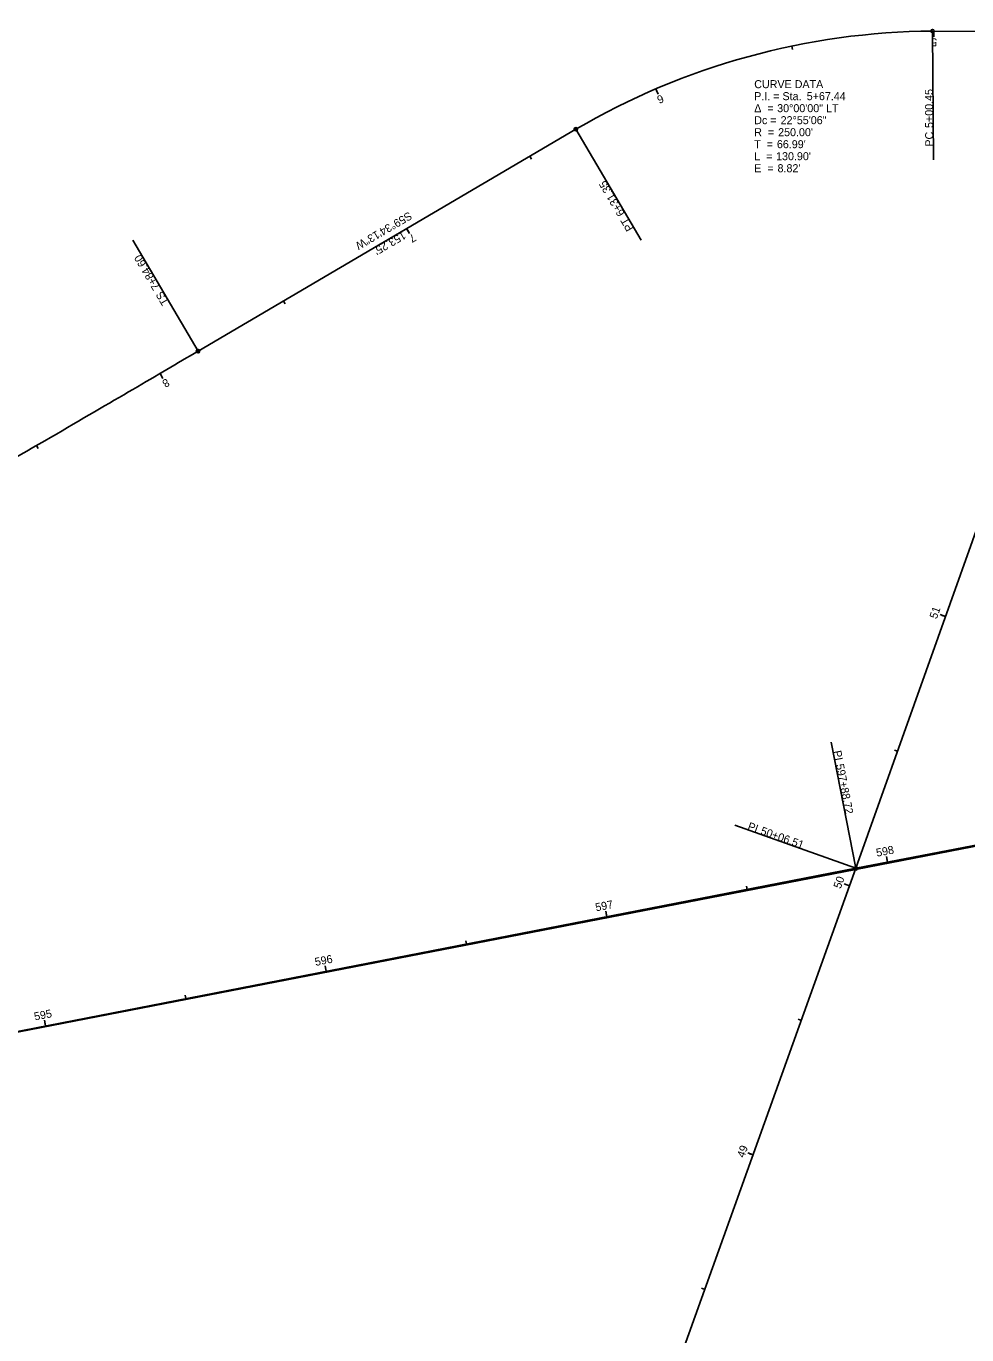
# Model space of a CAD drawing. Extents: x 2255781 to 2266449, y 734189 to 743342.
# Drawn here: x 2262943.9 to 2263272.9, y 741958.3 to 742416.1 of the extents above; entities that cross this region are included whole.
import ezdxf

# ---------------------------------------------------------------- set-up
doc = ezdxf.new("R2010")
doc.units = 0
for name, color, linetype in [('GE_X_Alignment', 7, 'Continuous'), ('GE_X_Alignment_1000_Bearings', 7, 'Continuous'), ('GE_X_Alignment_1000_Cardinal_Points', 7, 'Continuous'), ('GE_X_Alignment_1000_Curve_Data', 7, 'Continuous'), ('GE_X_Alignment_1000_Distances', 7, 'Continuous'), ('GE_X_Alignment_1000_Stations', 7, 'Continuous'), ('GE_X_Alignment_100_Bearings', 7, 'Continuous'), ('GE_X_Alignment_100_Cardinal_Points', 7, 'Continuous'), ('GE_X_Alignment_100_Curve_Data', 7, 'Continuous'), ('GE_X_Alignment_100_Distances', 7, 'Continuous'), ('GE_X_Alignment_100_Stations', 7, 'Continuous'), ('GE_X_Alignment_500_Bearings', 7, 'Continuous'), ('GE_X_Alignment_500_Cardinal_Points', 7, 'Continuous'), ('GE_X_Alignment_500_Curve_Data', 7, 'Continuous'), ('GE_X_Alignment_500_Distances', 7, 'Continuous'), ('GE_X_Alignment_500_Stations', 7, 'Continuous'), ('SC_Scratch4', 7, 'Continuous')]:
    doc.layers.add(name, color=color, linetype=linetype)

msp = doc.modelspace()

# ---------------------------------------------------------------- linework, layer by layer
at = {"layer": 'GE_X_Alignment'}
for p, q in [((2263234.07, 742121.49), (2263662.12, 743324.91)), ((2263338.12, 742414.02), (2263260.89, 742414.36)), ((2263234.07, 742121.49), (2264717.55, 742410.01)), ((2263136.12, 742380.02), (2263003.98, 742302.4)), ((2262524.08, 741983.4), (2263234.07, 742121.49)), ((2262767.69, 740821.08), (2263234.07, 742121.49))]:
    msp.add_line(p, q, dxfattribs=at)
msp.add_arc((2263262.59, 742164.37), 250, 90.3896, 120.3897, dxfattribs=at)
msp.add_open_spline([(2263003.98, 742302.4), (2262996.8, 742298.18), (2262982.43, 742289.73), (2262953.66, 742272.9), (2262917.56, 742252.1), (2262881.09, 742231.92), (2262851.61, 742216.36), (2262836.76, 742208.81), (2262829.3, 742205.1)], degree=3, dxfattribs=at)
at = {"layer": 'GE_X_Alignment_1000_Cardinal_Points'}
for p, q in [((2263260.89, 742414.36), (2263261.2, 742369.36)), ((2263136.12, 742380.02), (2263158.91, 742341.22)), ((2263003.98, 742302.4), (2262981.17, 742341.19)), ((2263234.07, 742121.49), (2263225.47, 742165.66)), ((2263234.07, 742121.49), (2263191.67, 742136.57))]:
    msp.add_line(p, q, dxfattribs=at)
for centre in [(2263260.89, 742414.36), (2263136.12, 742380.02), (2263003.98, 742302.4), (2263234.07, 742121.49), (2263234.07, 742121.49)]:
    msp.add_circle(centre, 0.6, dxfattribs=at)
at = {"layer": 'GE_X_Alignment_1000_Stations'}
for p, q in [((2263261.34, 742414.36), (2263261.34, 742413.16)), ((2263231.87, 742115.36), (2263229.98, 742116.04)), ((2262950.66, 742066.37), (2262950.43, 742067.55))]:
    msp.add_line(p, q, dxfattribs=at)
at = {"layer": 'GE_X_Alignment_100_Cardinal_Points'}
for p, q in [((2263260.89, 742414.36), (2263261.2, 742369.36)), ((2263136.12, 742380.02), (2263158.91, 742341.22)), ((2263003.98, 742302.4), (2262981.17, 742341.19)), ((2263234.07, 742121.49), (2263225.47, 742165.66)), ((2263234.07, 742121.49), (2263191.67, 742136.57))]:
    msp.add_line(p, q, dxfattribs=at)
for centre in [(2263260.89, 742414.36), (2263136.12, 742380.02), (2263003.98, 742302.4), (2263234.07, 742121.49), (2263234.07, 742121.49)]:
    msp.add_circle(centre, 0.6, dxfattribs=at)
at = {"layer": 'GE_X_Alignment_100_Stations'}
for p, q in [((2263261.34, 742414.36), (2263261.33, 742412.36)), ((2263211.7, 742409.13), (2263211.94, 742407.96)), ((2263164.09, 742394.14), (2263164.87, 742392.3)), ((2263120.04, 742370.57), (2263120.65, 742369.54)), ((2263076.93, 742345.25), (2263077.94, 742343.52)), ((2263033.82, 742319.92), (2263034.42, 742318.89)), ((2262990.7, 742294.6), (2262991.72, 742292.87)), ((2262947.52, 742269.4), (2262948.12, 742268.36)), ((2263265.4, 742209.57), (2263263.51, 742210.24)), ((2263248.64, 742162.46), (2263247.51, 742162.87)), ((2263245.14, 742123.64), (2263244.76, 742125.61)), ((2263231.87, 742115.36), (2263229.98, 742116.04)), ((2263196.06, 742114.1), (2263195.83, 742115.28)), ((2263146.98, 742104.55), (2263146.6, 742106.52)), ((2263097.9, 742095.01), (2263097.67, 742096.18)), ((2263048.82, 742085.46), (2263048.43, 742087.42)), ((2262999.74, 742075.91), (2262999.51, 742077.09)), ((2262950.66, 742066.37), (2262950.27, 742068.33)), ((2263214.99, 742068.3), (2263213.86, 742068.7)), ((2263198.11, 742021.23), (2263196.23, 742021.91)), ((2263181.23, 741974.17), (2263180.1, 741974.57))]:
    msp.add_line(p, q, dxfattribs=at)
at = {"layer": 'GE_X_Alignment_500_Cardinal_Points'}
for p, q in [((2263260.89, 742414.36), (2263261.2, 742369.36)), ((2263136.12, 742380.02), (2263158.91, 742341.22)), ((2263003.98, 742302.4), (2262981.17, 742341.19)), ((2263234.07, 742121.49), (2263225.47, 742165.66)), ((2263234.07, 742121.49), (2263191.67, 742136.57))]:
    msp.add_line(p, q, dxfattribs=at)
for centre in [(2263260.89, 742414.36), (2263136.12, 742380.02), (2263003.98, 742302.4), (2263234.07, 742121.49), (2263234.07, 742121.49)]:
    msp.add_circle(centre, 0.6, dxfattribs=at)
at = {"layer": 'GE_X_Alignment_500_Stations'}
for p, q in [((2263261.34, 742414.36), (2263261.33, 742412.36)), ((2263164.09, 742394.14), (2263164.56, 742393.04)), ((2263076.93, 742345.25), (2263077.54, 742344.21)), ((2262990.7, 742294.6), (2262991.31, 742293.56)), ((2263265.4, 742209.57), (2263264.27, 742209.98)), ((2263245.14, 742123.64), (2263244.91, 742124.82)), ((2263231.87, 742115.36), (2263229.98, 742116.04)), ((2263146.98, 742104.55), (2263146.75, 742105.73)), ((2263048.82, 742085.46), (2263048.59, 742086.64)), ((2262950.66, 742066.37), (2262950.27, 742068.33)), ((2263198.11, 742021.23), (2263196.98, 742021.64))]:
    msp.add_line(p, q, dxfattribs=at)
at = {"layer": 'SC_Scratch4'}
for p, q in [((2263234.07, 742121.1), (2264717.66, 742409.08)), ((2262524.04, 741983.27), (2263234.07, 742121.1))]:
    msp.add_line(p, q, dxfattribs=at)

# ---------------------------------------------------------------- texts
at = {"layer": 'GE_X_Alignment_1000_Bearings'}
msp.add_text('S59°34\'13"W', height=2.8, rotation=210.4298, dxfattribs=at).set_placement((2263077.76, 742351.3))
at = {"layer": 'GE_X_Alignment_1000_Cardinal_Points'}
for s, rotation, p in [('5+00.45', 90.3896, (2263261.07, 742380.47)), ('PC', 90.3896, (2263261.12, 742373.95)), ('6+31.35', 120.4298, (2263153.36, 742350.58)), ('PT', 120.4298, (2263156.44, 742345.34)), ('7+84.60', 120.4521, (2262990.81, 742324.71)), ('TS', 120.4521, (2262993.9, 742319.46)), ('PI', 281.0061, (2263226.15, 742162.43)), ('597+88.72', 281.0061, (2263227.06, 742157.74)), ('PI', 340.4195, (2263195.97, 742135.09)), ('50+06.51', 340.4195, (2263200.48, 742133.49))]:
    msp.add_text(s, height=2.8, rotation=rotation, dxfattribs=at).set_placement(p)
at = {"layer": 'GE_X_Alignment_1000_Curve_Data'}
for s, p in [('CURVE DATA', (2263198.51, 742394.39)), ('P.I. = Sta. ', (2263198.51, 742390.19)), ('5+67.44', (2263216.87, 742390.19)), ('Δ  = ', (2263198.51, 742385.99)), ('30°00\'00" LT', (2263206.53, 742385.99)), ('Dc = ', (2263198.51, 742381.79)), ('22°55\'06"', (2263207.74, 742381.79)), ('R  = ', (2263198.51, 742377.59)), ("250.00'", (2263206.87, 742377.59)), ('T  = ', (2263198.51, 742373.39)), ("66.99'", (2263206.44, 742373.39)), ('L  = ', (2263198.51, 742369.19)), ('E  = ', (2263198.51, 742364.99)), ("130.90'", (2263206.15, 742369.19)), ("8.82'", (2263206.66, 742364.99))]:
    msp.add_text(s, height=2.8, dxfattribs=at).set_placement(p)
at = {"layer": 'GE_X_Alignment_1000_Distances'}
msp.add_text("153.25'", height=2.8, rotation=210.4298, dxfattribs=at).set_placement((2263075.67, 742344.45))
at = {"layer": 'GE_X_Alignment_1000_Stations'}
msp.add_text('50', height=2.8, rotation=70.2703, dxfattribs=at).set_placement((2263228.73, 742114.16))
at = {"layer": 'GE_X_Alignment_100_Bearings'}
msp.add_text('S59°34\'13"W', height=2.8, rotation=210.4298, dxfattribs=at).set_placement((2263077.76, 742351.3))
at = {"layer": 'GE_X_Alignment_100_Cardinal_Points'}
for s, rotation, p in [('5+00.45', 90.3896, (2263261.07, 742380.47)), ('PC', 90.3896, (2263261.12, 742373.95)), ('6+31.35', 120.4298, (2263153.36, 742350.58)), ('PT', 120.4298, (2263156.44, 742345.34)), ('7+84.60', 120.4521, (2262990.81, 742324.71)), ('TS', 120.4521, (2262993.9, 742319.46)), ('PI', 281.0061, (2263226.15, 742162.43)), ('597+88.72', 281.0061, (2263227.06, 742157.74)), ('PI', 340.4195, (2263195.97, 742135.09)), ('50+06.51', 340.4195, (2263200.48, 742133.49))]:
    msp.add_text(s, height=2.8, rotation=rotation, dxfattribs=at).set_placement(p)
at = {"layer": 'GE_X_Alignment_100_Curve_Data'}
for s, p in [('CURVE DATA', (2263198.51, 742394.39)), ('P.I. = Sta. ', (2263198.51, 742390.19)), ('5+67.44', (2263216.87, 742390.19)), ('Δ  = ', (2263198.51, 742385.99)), ('30°00\'00" LT', (2263206.53, 742385.99)), ('Dc = ', (2263198.51, 742381.79)), ('22°55\'06"', (2263207.74, 742381.79)), ('R  = ', (2263198.51, 742377.59)), ("250.00'", (2263206.87, 742377.59)), ('T  = ', (2263198.51, 742373.39)), ("66.99'", (2263206.44, 742373.39)), ('L  = ', (2263198.51, 742369.19)), ('E  = ', (2263198.51, 742364.99)), ("130.90'", (2263206.15, 742369.19)), ("8.82'", (2263206.66, 742364.99))]:
    msp.add_text(s, height=2.8, dxfattribs=at).set_placement(p)
at = {"layer": 'GE_X_Alignment_100_Distances'}
msp.add_text("153.25'", height=2.8, rotation=210.4298, dxfattribs=at).set_placement((2263075.67, 742344.45))
at = {"layer": 'GE_X_Alignment_100_Stations'}
for s, rotation, p in [('5', 179.7497, (2263262.45, 742411.81)), ('6', 203.2048, (2263166.11, 742392.24)), ('7', 210.4298, (2263079.2, 742343.68)), ('8', 210.4283, (2262992.95, 742292.96)), ('51', 70.4195, (2263262.32, 742208.52)), ('598', 11.0061, (2263241.43, 742125.52)), ('50', 70.2703, (2263228.73, 742114.16)), ('597', 11.0061, (2263143.21, 742106.41)), ('596', 11.0061, (2263045.11, 742087.33)), ('595', 11.0061, (2262946.94, 742068.24)), ('49', 70.2703, (2263194.98, 742020.05))]:
    msp.add_text(s, height=2.8, rotation=rotation, dxfattribs=at).set_placement(p)
at = {"layer": 'GE_X_Alignment_500_Bearings'}
msp.add_text('S59°34\'13"W', height=2.8, rotation=210.4298, dxfattribs=at).set_placement((2263077.76, 742351.3))
at = {"layer": 'GE_X_Alignment_500_Cardinal_Points'}
for s, rotation, p in [('5+00.45', 90.3896, (2263261.07, 742380.47)), ('PC', 90.3896, (2263261.12, 742373.95)), ('6+31.35', 120.4298, (2263153.36, 742350.58)), ('PT', 120.4298, (2263156.44, 742345.34)), ('7+84.60', 120.4521, (2262990.81, 742324.71)), ('TS', 120.4521, (2262993.9, 742319.46)), ('PI', 281.0061, (2263226.15, 742162.43)), ('597+88.72', 281.0061, (2263227.06, 742157.74)), ('PI', 340.4195, (2263195.97, 742135.09)), ('50+06.51', 340.4195, (2263200.48, 742133.49))]:
    msp.add_text(s, height=2.8, rotation=rotation, dxfattribs=at).set_placement(p)
at = {"layer": 'GE_X_Alignment_500_Curve_Data'}
for s, p in [('CURVE DATA', (2263198.51, 742394.39)), ('P.I. = Sta. ', (2263198.51, 742390.19)), ('5+67.44', (2263216.87, 742390.19)), ('Δ  = ', (2263198.51, 742385.99)), ('30°00\'00" LT', (2263206.53, 742385.99)), ('Dc = ', (2263198.51, 742381.79)), ('22°55\'06"', (2263207.74, 742381.79)), ('R  = ', (2263198.51, 742377.59)), ("250.00'", (2263206.87, 742377.59)), ('T  = ', (2263198.51, 742373.39)), ("66.99'", (2263206.44, 742373.39)), ('L  = ', (2263198.51, 742369.19)), ('E  = ', (2263198.51, 742364.99)), ("130.90'", (2263206.15, 742369.19)), ("8.82'", (2263206.66, 742364.99))]:
    msp.add_text(s, height=2.8, dxfattribs=at).set_placement(p)
at = {"layer": 'GE_X_Alignment_500_Distances'}
msp.add_text("153.25'", height=2.8, rotation=210.4298, dxfattribs=at).set_placement((2263075.67, 742344.45))
at = {"layer": 'GE_X_Alignment_500_Stations'}
for s, rotation, p in [('5', 179.7497, (2263262.45, 742411.81)), ('50', 70.2703, (2263228.73, 742114.16)), ('595', 11.0061, (2262946.94, 742068.24))]:
    msp.add_text(s, height=2.8, rotation=rotation, dxfattribs=at).set_placement(p)

doc.saveas('drawing.dxf')
